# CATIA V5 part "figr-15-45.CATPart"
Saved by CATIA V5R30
Part number: Part1
Bounding box of the stored display mesh (mm): x 2.5 to 37.676, y -21.475 to 20.775, z 0 to 35.904
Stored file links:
  D:\PROJECTS\CATIA V56R 2020\Resources\Parts File\c15_catia_v5_6r2020_prt\figr-15-45.CATPart
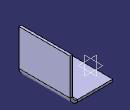
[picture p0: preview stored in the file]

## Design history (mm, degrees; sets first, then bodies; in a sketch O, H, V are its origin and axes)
SheetMetalParameters1: Thickness 2, BendRadius 4, KFactor 0.400515 {= log(min(100,max(20*SheetMetalParameters1.BendRadius,SheetMetalParameters1.Thickness)/SheetMetalParameters1.Thickness))/log(100)/2}, ReliefRadialLength 1, ReliefAxialLength 2, MinimumBendRadius 0
Body1 (main body)
  Sketch1 on xy-plane, origin (0, 0, 0), H (1, 0, 0), V (0, 1, 0)
    line L1 (2.4998, 20.7748) -> (69.1212, 20.7748)
    line L2 (69.1212, 20.7748) -> (69.1212, -21.4753)
    line L3 (69.1212, -21.4753) -> (2.4998, -21.4753)
    line L4 (2.4998, -21.4753) -> (2.4998, 20.7748)
    horizontal: L1 H, L3 H
    vertical: L2 V, L4 V
  Wall1: Thickness 2, Profile Sketch1, OffsetValue 0
  Sketch2 on face of Wall1, origin (0, 0, 2), H (1, 0, 0), V (0, 1, 0)
    line L1 (35.4466, 20.5889) -> (35.4466, -21.306)
    vertical: L1 V
  FlatBend1: Angle 90, Axis Sketch2, FixedPoint vertex [face of Wall1 | face of Wall1 | face of Wall1], KFactor 0.400515 {= log(min(100,max(20*FlatBend1.FlatBendRadius,SheetMetalParameters1.Thickness)/SheetMetalParameters1.Thickness))/log(100)/2}, Radius 4 {= SheetMetalParameters1.BendRadius}
  Unfold1: FoldUnfold_Angles 90, FoldUnfold_FoldUnfoldFaces face of FlatBend1, FoldUnfold_ReferenceFaces face of Wall1
  Fold1: FoldUnfold_Angles 90, FoldUnfold_FoldUnfoldFaces face of FlatBend1, FoldUnfold_ReferenceFaces face of Wall1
